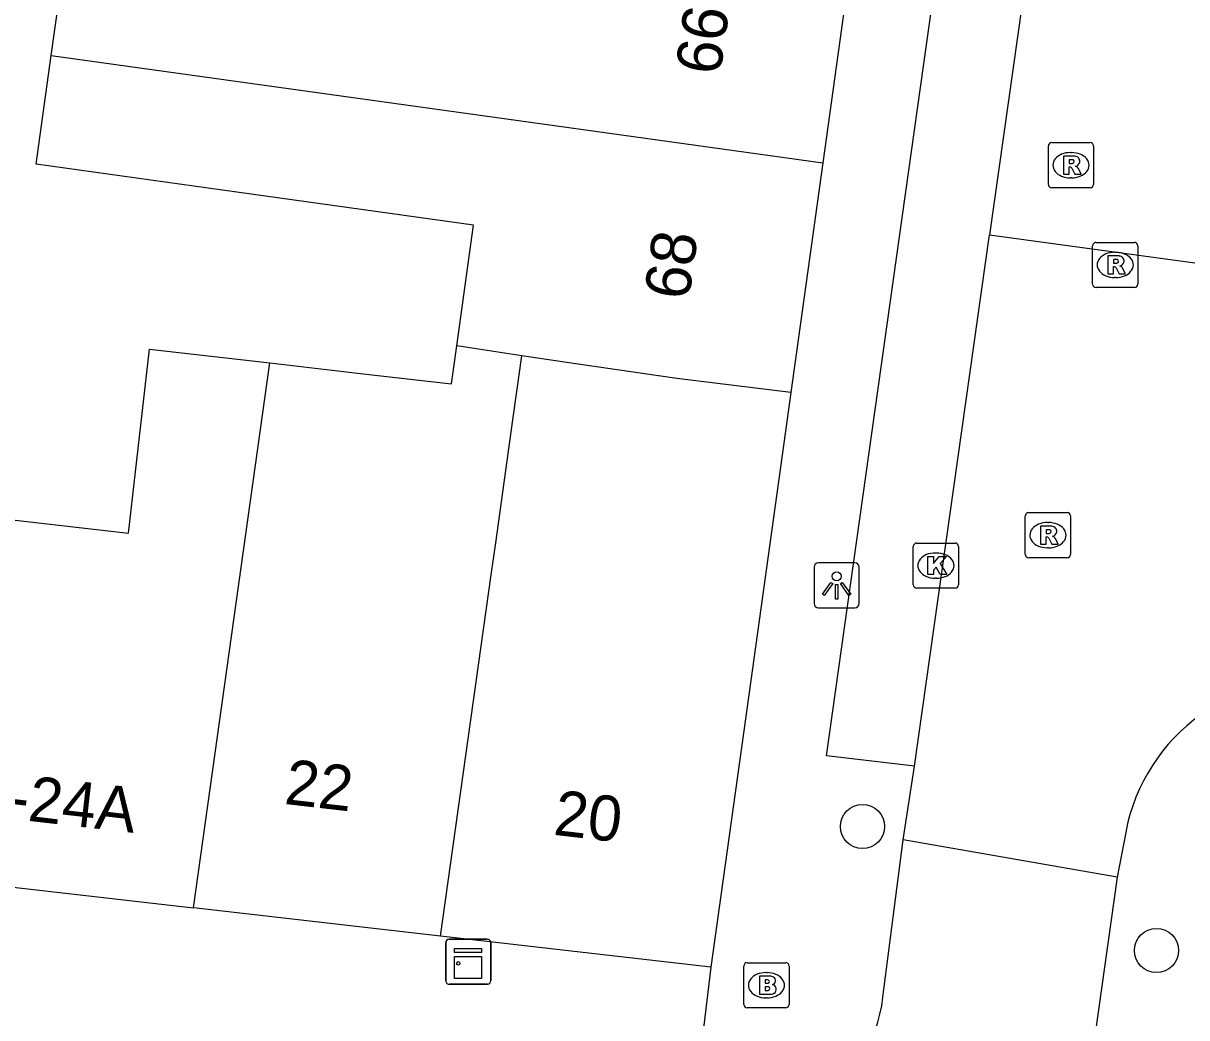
# Model space of a CAD drawing. Extents: x 161696 to 162377, y 380761 to 381673.
# Drawn here: x 161959.34 to 161985.12, y 381399.74 to 381421.78 of the extents above; entities that cross this region are included whole.
import ezdxf

# ---------------------------------------------------------------- set-up
doc = ezdxf.new("R2010")
doc.units = 0
for name, color, linetype in [('IMGEO_Boom', 7, 'Continuous'), ('IMGEO_Brandkraan', 7, 'Continuous'), ('IMGEO_Kast', 7, 'Continuous'), ('IMGEO_Kolk', 7, 'Continuous'), ('IMGEO_Lichtpunt', 7, 'Continuous'), ('IMGEO_Pand', 7, 'Continuous'), ('IMGEO_Pand_nummerreeks', 7, 'Continuous'), ('IMGEO_Rijbaan_lokaal_open', 7, 'Continuous'), ('IMGEO_Rioolput', 7, 'Continuous'), ('IMGEO_Voetpad_open', 7, 'Continuous')]:
    doc.layers.add(name, color=color, linetype=linetype)

msp = doc.modelspace()

# ---------------------------------------------------------------- linework, layer by layer
at = {"layer": 'IMGEO_Boom'}
for centre in [(161977.934, 381403.978), (161984.446, 381401.229)]:
    msp.add_circle(centre, 0.489, dxfattribs=at)
at = {"layer": 'IMGEO_Brandkraan'}
for p, q in [((161975.305, 381400.034), (161975.305, 381400.886)), ((161975.38, 381400.96), (161976.232, 381400.96)), ((161976.306, 381400.886), (161976.306, 381400.034)), ((161975.793, 381400.74), (161975.818, 381400.74)), ((161975.816, 381400.18), (161975.791, 381400.18)), ((161976.232, 381399.96), (161975.38, 381399.96))]:
    msp.add_line(p, q, dxfattribs=at)
for points in [[(161975.305, 381400.034), (161975.305, 381400.886)], [(161975.38, 381400.96), (161976.232, 381400.96)], [(161976.306, 381400.886), (161976.306, 381400.034)], [(161975.653, 381400.66), (161975.653, 381400.26), (161975.866, 381400.26)], [(161975.884, 381400.66), (161975.653, 381400.66)], [(161975.832, 381400.579), (161975.778, 381400.579), (161975.778, 381400.503)], [(161975.778, 381400.503), (161975.831, 381400.503)], [(161975.84, 381400.427), (161975.778, 381400.427), (161975.778, 381400.346)], [(161975.778, 381400.346), (161975.84, 381400.346)], [(161976.232, 381399.96), (161975.38, 381399.96)]]:
    msp.add_lwpolyline(points, dxfattribs=at)
for centre, radius, start, end in [((161975.382, 381400.884), 0.0765, 91.552, 178.448), ((161975.382, 381400.884), 0.0765, 91.552, 178.448), ((161976.23, 381400.884), 0.0765, 1.552, 88.448), ((161976.23, 381400.884), 0.0765, 1.552, 88.448), ((161975.833, 381400.541), 0.0379, 267.8285, 90.9355), ((161975.888, 381400.515), 0.145, 59.4692, 91.5367), ((161975.913, 381400.562), 0.0922, 285.5137, 58.1501), ((161975.841, 381400.386), 0.0404, 269.8759, 90.5077), ((161975.918, 381400.37), 0.105, 301.3115, 78.989), ((161975.382, 381400.036), 0.0765, 181.552, 268.448), ((161975.382, 381400.036), 0.0765, 181.552, 268.448), ((161975.872, 381400.511), 0.251, 268.6676, 293.5347), ((161976.23, 381400.036), 0.0765, 271.552, 358.448), ((161976.23, 381400.036), 0.0765, 271.552, 358.448)]:
    msp.add_arc(centre, radius, start, end, dxfattribs=at)
for centre, major_axis, ratio, start_param, end_param in [((161975.792, 381400.46), (-0.387, 0.002), 0.722429, 4.712389, 7.853982), ((161975.817, 381400.46), (-0.39, 0.002), 0.717154, 1.570796, 4.712389)]:
    msp.add_ellipse(centre, major_axis=major_axis, ratio=ratio, start_param=start_param, end_param=end_param, dxfattribs=at)
at = {"layer": 'IMGEO_Kast'}
for p, q in [((161968.699, 381400.556), (161968.699, 381401.397)), ((161968.699, 381401.397), (161968.699, 381400.556)), ((161968.774, 381401.481), (161969.615, 381401.481)), ((161969.615, 381401.481), (161968.774, 381401.481)), ((161969.699, 381401.406), (161969.699, 381400.565)), ((161969.699, 381400.565), (161969.699, 381401.406)), ((161969.624, 381400.481), (161968.783, 381400.481)), ((161968.783, 381400.481), (161969.624, 381400.481))]:
    msp.add_line(p, q, dxfattribs=at)
for points in [[(161968.894, 381401.271), (161969.494, 381401.271), (161969.494, 381401.186), (161968.894, 381401.186), (161968.894, 381401.271)], [(161968.894, 381401.096), (161969.494, 381401.096), (161969.494, 381400.607), (161968.894, 381400.607), (161968.894, 381401.096)]]:
    msp.add_lwpolyline(points, dxfattribs=at)
msp.add_circle((161968.978, 381400.945), 0.0377, dxfattribs=at)
for centre, start, end in [((161968.777, 381401.403), 92.4484, 184.2845), ((161968.777, 381401.403), 92.4484, 184.2845), ((161969.621, 381401.403), 2.4484, 94.2845), ((161969.621, 381401.403), 2.4484, 94.2845), ((161968.777, 381400.559), 182.4484, 274.2845), ((161968.777, 381400.559), 182.4484, 274.2845), ((161969.621, 381400.559), 272.4484, 4.2845), ((161969.621, 381400.559), 272.4484, 4.2845)]:
    msp.add_arc(centre, 0.0779, start, end, dxfattribs=at)
at = {"layer": 'IMGEO_Kolk'}
for p, q in [((161979.059, 381409.332), (161979.059, 381410.184)), ((161979.134, 381410.258), (161979.986, 381410.258)), ((161980.06, 381410.184), (161980.06, 381409.332)), ((161979.547, 381410.038), (161979.572, 381410.038)), ((161979.57, 381409.478), (161979.545, 381409.478)), ((161979.986, 381409.258), (161979.134, 381409.258))]:
    msp.add_line(p, q, dxfattribs=at)
for points in [[(161979.059, 381409.332), (161979.059, 381410.184)], [(161979.134, 381410.258), (161979.986, 381410.258)], [(161980.06, 381410.184), (161980.06, 381409.332)], [(161979.38, 381409.958), (161979.503, 381409.958), (161979.503, 381409.807), (161979.633, 381409.958), (161979.797, 381409.958), (161979.651, 381409.807), (161979.804, 381409.558), (161979.652, 381409.558), (161979.567, 381409.722), (161979.503, 381409.655), (161979.503, 381409.558), (161979.38, 381409.558), (161979.38, 381409.958)], [(161979.986, 381409.258), (161979.134, 381409.258)]]:
    msp.add_lwpolyline(points, dxfattribs=at)
for centre, start, end in [((161979.136, 381410.182), 91.552, 178.448), ((161979.136, 381410.182), 91.552, 178.448), ((161979.984, 381410.182), 1.552, 88.448), ((161979.984, 381410.182), 1.552, 88.448), ((161979.136, 381409.334), 181.552, 268.448), ((161979.136, 381409.334), 181.552, 268.448), ((161979.984, 381409.334), 271.552, 358.448), ((161979.984, 381409.334), 271.552, 358.448)]:
    msp.add_arc(centre, 0.0765, start, end, dxfattribs=at)
for centre, major_axis, ratio, start_param, end_param in [((161979.546, 381409.758), (-0.387, 0.002), 0.722429, 4.712389, 7.853982), ((161979.571, 381409.758), (-0.39, 0.002), 0.717154, 1.570796, 4.712389)]:
    msp.add_ellipse(centre, major_axis=major_axis, ratio=ratio, start_param=start_param, end_param=end_param, dxfattribs=at)
at = {"layer": 'IMGEO_Lichtpunt'}
for p, q in [((161976.861, 381409.723), (161976.861, 381408.916)), ((161976.861, 381409.723), (161976.861, 381408.916)), ((161977.763, 381409.818), (161976.955, 381409.818)), ((161977.763, 381409.818), (161976.955, 381409.818)), ((161977.857, 381408.916), (161977.857, 381409.723)), ((161977.857, 381408.916), (161977.857, 381409.723)), ((161976.955, 381408.822), (161977.763, 381408.822)), ((161976.955, 381408.822), (161977.763, 381408.822))]:
    msp.add_line(p, q, dxfattribs=at)
for points in [[(161977.235, 381409.387), (161977.274, 381409.359), (161977.086, 381409.097), (161977.048, 381409.124), (161977.235, 381409.387)], [(161977.337, 381409.339), (161977.384, 381409.339), (161977.384, 381409.017), (161977.337, 381409.017), (161977.337, 381409.339)], [(161977.447, 381409.359), (161977.485, 381409.386), (161977.672, 381409.124), (161977.633, 381409.096), (161977.447, 381409.359)]]:
    msp.add_lwpolyline(points, dxfattribs=at)
msp.add_circle((161977.36, 381409.521), 0.0994, dxfattribs=at)
for centre, start, end in [((161976.955, 381409.723), 90, 180), ((161976.955, 381409.723), 90, 180), ((161977.763, 381409.723), 0, 90), ((161977.763, 381409.723), 0, 90), ((161976.955, 381408.916), 180, 270), ((161976.955, 381408.916), 180, 270), ((161977.763, 381408.916), 270, 0), ((161977.763, 381408.916), 270, 360)]:
    msp.add_arc(centre, 0.0946, start, end, dxfattribs=at)
at = {"layer": 'IMGEO_Pand'}
for points in [[(161959.959, 381421.059), (161960.31, 381423.583), (161964.441, 381423.008), (161969.929, 381422.244), (161970.259, 381424.62)], [(161977.737, 381423.578), (161977.055, 381418.68)], [(161968.944, 381414.625), (161969.316, 381417.303), (161963.755, 381418.078), (161959.624, 381418.654), (161959.959, 381421.059)], [(161959.959, 381421.059), (161977.055, 381418.68)], [(161977.055, 381418.68), (161976.347, 381413.594)], [(161958.322, 381410.864), (161961.671, 381410.479), (161962.141, 381414.555), (161964.8, 381414.249)], [(161964.8, 381414.249), (161966.69, 381414.032), (161967.198, 381413.973), (161968.827, 381413.786), (161968.944, 381414.625)], [(161970.388, 381414.409), (161968.944, 381414.625)], [(161963.109, 381402.173), (161964.8, 381414.249)], [(161968.586, 381401.544), (161969.708, 381409.554), (161969.807, 381410.263), (161970.189, 381412.989), (161970.277, 381413.619), (161970.388, 381414.409)], [(161976.347, 381413.594), (161973.821, 381413.903), (161971.531, 381414.24), (161970.388, 381414.409)], [(161976.347, 381413.594), (161976.228, 381412.739), (161975.295, 381406.042), (161974.573, 381400.857)], [(161957.243, 381402.847), (161963.109, 381402.173)], [(161968.586, 381401.544), (161963.109, 381402.173)], [(161974.573, 381400.857), (161968.586, 381401.544)]]:
    msp.add_lwpolyline(points, dxfattribs=at)
at = {"layer": 'IMGEO_Rijbaan_lokaal_open'}
for points in [[(161982.09, 381426.603), (161980.747, 381417.09)], [(161979.084, 381405.317), (161980.747, 381417.09)], [(161980.747, 381417.09), (161985.46, 381416.445)], [(161978.836, 381403.684), (161979.084, 381405.317)], [(161978.387, 381400.194), (161978.836, 381403.684)], [(161983.574, 381402.858), (161978.836, 381403.684)], [(161983.764, 381403.842), (161983.574, 381402.858)], [(161983.574, 381402.858), (161982.065, 381392.091), (161981.891, 381390.474)]]:
    msp.add_lwpolyline(points, dxfattribs=at)
for centre, radius, start, end in [((161987.855, 381403.075), 4.162, 82.1234, 169.3857), ((161974.631, 381400.671), 3.786, 261.9388, 352.7656)]:
    msp.add_arc(centre, radius, start, end, dxfattribs=at)
at = {"layer": 'IMGEO_Rioolput'}
for p, q in [((161982.126, 381419.131), (161982.978, 381419.131)), ((161982.051, 381418.205), (161982.051, 381419.057)), ((161982.539, 381418.911), (161982.564, 381418.911)), ((161983.052, 381419.057), (161983.052, 381418.205)), ((161982.562, 381418.351), (161982.537, 381418.351)), ((161982.978, 381418.131), (161982.126, 381418.131)), ((161983.032, 381415.995), (161983.032, 381416.847)), ((161983.107, 381416.921), (161983.959, 381416.921)), ((161984.033, 381416.847), (161984.033, 381415.995)), ((161983.52, 381416.701), (161983.545, 381416.701)), ((161983.543, 381416.141), (161983.518, 381416.141)), ((161983.959, 381415.921), (161983.107, 381415.921)), ((161981.541, 381410.007), (161981.541, 381410.859)), ((161981.616, 381410.933), (161982.468, 381410.933)), ((161982.542, 381410.859), (161982.542, 381410.007)), ((161982.029, 381410.713), (161982.054, 381410.713)), ((161982.052, 381410.153), (161982.027, 381410.153)), ((161982.468, 381409.933), (161981.616, 381409.933))]:
    msp.add_line(p, q, dxfattribs=at)
for points in [[(161982.126, 381419.131), (161982.978, 381419.131)], [(161982.051, 381418.205), (161982.051, 381419.057)], [(161983.052, 381419.057), (161983.052, 381418.205)], [(161982.64, 381418.829), (161982.388, 381418.831), (161982.388, 381418.431)], [(161982.388, 381418.431), (161982.512, 381418.431), (161982.512, 381418.593), (161982.523, 381418.593)], [(161982.566, 381418.75), (161982.512, 381418.75), (161982.512, 381418.669)], [(161982.512, 381418.669), (161982.564, 381418.669)], [(161982.57, 381418.564), (161982.641, 381418.431), (161982.781, 381418.431), (161982.716, 381418.557)], [(161982.978, 381418.131), (161982.126, 381418.131)], [(161983.032, 381415.995), (161983.032, 381416.847)], [(161983.107, 381416.921), (161983.959, 381416.921)], [(161984.033, 381416.847), (161984.033, 381415.995)], [(161983.621, 381416.619), (161983.369, 381416.621), (161983.369, 381416.221)], [(161983.547, 381416.54), (161983.493, 381416.54), (161983.493, 381416.459)], [(161983.369, 381416.221), (161983.493, 381416.221), (161983.493, 381416.383), (161983.504, 381416.383)], [(161983.493, 381416.459), (161983.545, 381416.459)], [(161983.551, 381416.354), (161983.622, 381416.221), (161983.762, 381416.221), (161983.697, 381416.347)], [(161983.959, 381415.921), (161983.107, 381415.921)], [(161981.541, 381410.007), (161981.541, 381410.859)], [(161981.616, 381410.933), (161982.468, 381410.933)], [(161982.542, 381410.859), (161982.542, 381410.007)], [(161982.13, 381410.631), (161981.878, 381410.633), (161981.878, 381410.233)], [(161981.878, 381410.233), (161982.002, 381410.233), (161982.002, 381410.395), (161982.013, 381410.395)], [(161982.056, 381410.552), (161982.002, 381410.552), (161982.002, 381410.471)], [(161982.002, 381410.471), (161982.054, 381410.471)], [(161982.06, 381410.366), (161982.131, 381410.233), (161982.271, 381410.233), (161982.206, 381410.359)], [(161982.468, 381409.933), (161981.616, 381409.933)]]:
    msp.add_lwpolyline(points, dxfattribs=at)
for centre, radius, start, end in [((161982.128, 381419.055), 0.0765, 91.552, 178.448), ((161982.128, 381419.055), 0.0765, 91.552, 178.448), ((161982.976, 381419.055), 0.0765, 1.552, 88.448), ((161982.976, 381419.055), 0.0765, 1.552, 88.448), ((161982.522, 381418.54), 0.0533, 26.0293, 88.6989), ((161982.548, 381418.858), 0.19, 274.7715, 282.9687), ((161982.572, 381418.654), 0.0964, 77.0061, 93.1865), ((161982.586, 381418.711), 0.0378, 276.6634, 79.6772), ((161982.639, 381418.719), 0.109, 350.3612, 89.416), ((161982.637, 381418.719), 0.112, 277.5842, 350.9817), ((161982.621, 381418.504), 0.108, 29.5134, 73.7905), ((161982.128, 381418.207), 0.0765, 181.552, 268.448), ((161982.128, 381418.207), 0.0765, 181.552, 268.448), ((161982.976, 381418.207), 0.0765, 271.552, 358.448), ((161982.976, 381418.207), 0.0765, 271.552, 358.448), ((161983.109, 381416.845), 0.0765, 91.552, 178.448), ((161983.109, 381416.845), 0.0765, 91.552, 178.448), ((161983.957, 381416.845), 0.0765, 1.552, 88.448), ((161983.957, 381416.845), 0.0765, 1.552, 88.448), ((161983.553, 381416.444), 0.0964, 77.0061, 93.1865), ((161983.567, 381416.501), 0.0378, 276.6634, 79.6772), ((161983.62, 381416.509), 0.109, 350.3612, 89.416), ((161983.503, 381416.33), 0.0533, 26.0293, 88.6989), ((161983.529, 381416.648), 0.19, 274.7715, 282.9687), ((161983.618, 381416.509), 0.112, 277.5842, 350.9817), ((161983.602, 381416.294), 0.108, 29.5134, 73.7905), ((161983.109, 381415.997), 0.0765, 181.552, 268.448), ((161983.109, 381415.997), 0.0765, 181.552, 268.448), ((161983.957, 381415.997), 0.0765, 271.552, 358.448), ((161983.957, 381415.997), 0.0765, 271.552, 358.448), ((161981.618, 381410.857), 0.0765, 91.552, 178.448), ((161981.618, 381410.857), 0.0765, 91.552, 178.448), ((161982.466, 381410.857), 0.0765, 1.552, 88.448), ((161982.466, 381410.857), 0.0765, 1.552, 88.448), ((161982.129, 381410.521), 0.109, 350.3612, 89.416), ((161982.012, 381410.342), 0.0533, 26.0293, 88.6989), ((161982.038, 381410.66), 0.19, 274.7715, 282.9687), ((161982.062, 381410.456), 0.0964, 77.0061, 93.1865), ((161982.076, 381410.513), 0.0378, 276.6634, 79.6772), ((161982.127, 381410.521), 0.112, 277.5842, 350.9817), ((161982.111, 381410.306), 0.108, 29.5134, 73.7905), ((161981.618, 381410.009), 0.0765, 181.552, 268.448), ((161981.618, 381410.009), 0.0765, 181.552, 268.448), ((161982.466, 381410.009), 0.0765, 271.552, 358.448), ((161982.466, 381410.009), 0.0765, 271.552, 358.448)]:
    msp.add_arc(centre, radius, start, end, dxfattribs=at)
for centre, major_axis, ratio, start_param, end_param in [((161982.538, 381418.631), (-0.387, 0.002), 0.722429, 4.712389, 7.853982), ((161982.563, 381418.631), (-0.39, 0.002), 0.717154, 1.570796, 4.712389), ((161983.519, 381416.421), (-0.387, 0.002), 0.722429, 4.712389, 7.853982), ((161983.544, 381416.421), (-0.39, 0.002), 0.717154, 1.570796, 4.712389), ((161982.028, 381410.433), (-0.387, 0.002), 0.722429, 4.712389, 7.853982), ((161982.053, 381410.433), (-0.39, 0.002), 0.717154, 1.570796, 4.712389)]:
    msp.add_ellipse(centre, major_axis=major_axis, ratio=ratio, start_param=start_param, end_param=end_param, dxfattribs=at)
at = {"layer": 'IMGEO_Voetpad_open'}
for points in [[(161979.084, 381405.317), (161977.137, 381405.545), (161980.028, 381426.133)], [(161974.573, 381400.857), (161974.1, 381396.922)]]:
    msp.add_lwpolyline(points, dxfattribs=at)

# ---------------------------------------------------------------- texts
at = {"layer": 'IMGEO_Pand_nummerreeks'}
for s, rotation, p in [('66', 82.0731, (161974.778, 381420.605)), ('68', 82.0705, (161974.085, 381415.621)), ('22', 353.4511, (161965.105, 381404.48)), ('24-24A', 353.4454, (161957.502, 381404.327)), ('20', 353.4511, (161971.066, 381403.796))]:
    msp.add_text(s, height=1, rotation=rotation, dxfattribs=at).set_placement(p)

doc.saveas('drawing.dxf')
